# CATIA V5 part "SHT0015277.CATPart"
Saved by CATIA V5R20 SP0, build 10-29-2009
Part number: SHT00105277
Source: Unknown
Bounding box of the stored display mesh (mm): x 989.999 to 1508.999, y -744.979 to -424.979, z 20 to 152.7
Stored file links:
  E:\李燕龙\吉利商用车G3\07 设计变更\ECR0009849--标配底支架后移50mm设计变更\数据图纸\SHT0015277.CATPart
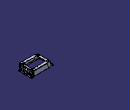
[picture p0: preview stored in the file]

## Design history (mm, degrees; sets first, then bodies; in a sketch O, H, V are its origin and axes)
Set1
  Plane1 to Plane3: stored without definition
  Sketch1 on Plane3, origin (0, -584.9794, 0), H (-1, 0, 0), V (0, 0, 1)
    point P1 (-1154.999, 150.4998)
    line L1 (-1154.999, 150.4998) -> (-1094.999, 150.4998)
    point P2 (-1094.999, 150.4998)
    line L2 (-1094.999, 150.4998) -> (-1034.999, 21.9998)
    point P3 (-1034.999, 21.9998)
    line L3 (-1034.999, 21.9998) -> (-989.999, 21.9998)
    point P4 (-989.999, 21.9998)
    reference projected line E1 (-999.999, 19.9998) -> (-1029.999, 19.9998) from edge [face of Solid11 | face of Solid11]
    reference intersected line E2 through (-1094.999, 0) direction (0, -1) from Plane1
    reference intersected line E3 through (-1034.999, 0) direction (0, -1) from Plane2
    distance L3 E1 = 2
    distance P3 E2 = 60
    distance L1 L3 = 128.5
    distance P2 E3 = 60
    distance P1 P2 = 60
    distance P3 P4 = 45
    horizontal: L1 H, L3 H
    coincidence: L1 P2, L2 P2, L2 P3, L3 P3
  Plane4: stored without definition
  Line1: stored without definition
  DatumSurface1
  DatumCurve1
  DatumSurface2
  DatumSurface3
  Plane5: stored without definition
  Plane6: stored without definition
  DatumCurve2 to DatumCurve5
  Plane7: stored without definition
  DatumPoint1
  DatumPoint2
  DatumCurve6
  DatumCurve7
  Plane8: stored without definition
  Sketch2 on Plane8, origin (225.7297, 0, 484.3783), H (0, 1, 0), V (-0.9064, 0, 0.4224)
    circle A1 centre (-484.2109, -918.6821) radius 1.5
    radius A1 = 1.5
  Plane9: stored without definition
  Sketch3 on Plane9, origin (1057.8408, -768.5663, 0), H (0.5878, 0.809, 0), V (0, 0, 1)
    circle A1 centre (77.1406, 149.6484) radius 1.5
    radius A1 = 1.5
Body1 "SHT0015277.1\\lianjei_AllCATPart.1\\四方焊接螺母.1\\几何体.3" (main body)
  Solid1: solid without history
  Translate1: ToTransfor Solid1, Direction (1, 0, 0), Length 45
  Sketch4 on Plane3, origin (0, -584.9794, 0), H (-1, 0, 0), V (0, 0, 1)
    point P1 (-1143.999, 149.9998)
    line L1 (-1143.999, 149.9998) -> (-1079.999, 149.9998)
    point P2 (-1079.999, 149.9998)
    construction line L2 (-1079.999, 149.9998) -> (-1031.999, 21.9998)
    point P3 (-1031.999, 21.9998)
    line L3 (-1031.999, 21.9998) -> (-989.999, 21.9998)
    point P4 (-989.999, 21.9998)
    reference projected line E1 (-999.999, 19.9998) -> (-1029.999, 19.9998) from edge [face of Solid11 | face of Solid11]
    reference intersected line E2 through (-1094.999, 0) direction (0, -1) from Plane1
    reference intersected line E3 through (-1034.999, 0) direction (0, -1) from Plane2
    line L4 (-1031.999, 21.9998) -> (-1031.999, 46.9998)
    line L5 (-1031.999, 46.9998) -> (-1079.999, 149.9998)
    distance L3 E1 = 2
    distance P3 E2 = 63
    distance L1 L3 = 128
    distance P2 E3 = 45
    distance P1 P2 = 64
    length L4 = 25
    distance P4 P2 H = 90
    horizontal: L1 H, L3 H
    coincidence: L1 P2, L2 P2, L2 P3, L3 P3
    vertical: L4 V
  Sketch5 on Plane2, origin (1034.999, 0, 0), H (0, 1, 0), V (0, 0, 1)
    line L1 (-687.3238, 162.0698) -> (-674.986, 140.7001)
    line L2 (-674.986, 140.7001) -> (-494.986, 140.7001)
    line L3 (-494.986, 140.7001) -> (-481.1375, 164.6862)
    line L4 (-481.1375, 164.6862) -> (-687.3238, 162.0698)
    reference projected line E1 (-670.3672, 140.7001) -> (-499.6048, 140.7001) from edge [face of Solid7 | face of Solid7]
    reference projected line E2 (-677.2954, 144.7001) -> (-678.4501, 146.7001) from edge [face of Solid7 | face of Solid7]
    reference projected line E3 (-492.6766, 144.7001) -> (-491.5219, 146.7001) from edge [face of Solid7 | face of Solid7]
    coincidence: L2 E1, L1 E2, L3 E3
  Sketch6 on face of Pad6, origin (0, 0, 147.9998), H (1, 0, 0), V (0, -1, 0)
    circle A1 centre (1128.999, 469.9941) radius 4.5
    point P2 (1449.999, 469.9941)
    reference projected arc E1 centre (1449.999, 469.9941) radius 4.105 from (1445.9992, 470.9175) to (1453.9988, 469.0707) ccw from edge [face of Solid2 | face of Solid2]
    construction line L1 (1449.999, 469.9941) -> (1128.999, 469.9941)
    circle A2 centre (1007.999, 469.9794) radius 5
    point P3 (1007.999, 469.9794)
    reference projected arc E2 centre (1007.999, 469.9794) radius 5 from (1012.999, 469.9794) to (1007.999, 474.9794) ccw from edge [face of Solid11 | face of Solid11]
    radius A1 = 4.5
    length L1 = 321
    radius A2 = 5
    concentricity: P2 E1, P3 E2
    horizontal: L1 H
Body2
  ThickSurface1: Surface DatumSurface2, TopOffset 2, BotOffset 0
Body3
  Pad1: profile Sketch1, direction (0, 1, 0), length 154, mirrored extent, thin wall 2
  Body4
    Pad2: profile Sketch11, direction (1, 0, 0), up to face of Pad1, thin wall 0, second thickness 2
  Trim1: tool Body4, faces to remove face of Pad2
  Body5
    Pad3: profile Sketch7, direction (-1, 0, 0), up to face of Pad1, opposite side length 154, thin wall 2
    Mirror1: of Pad3, Sketch7, about Plane3
  Trim2: tool Body5
  Sketch7 on Plane2, origin (1034.999, 0, 0), H (0, 1, 0), V (0, 0, 1)
    line L1 (-698.0895, 9.5681) -> (-681.6575, 26.0001)
    line L2 (-681.6575, 26.0001) -> (-621.6575, 26.0001)
    line L3 (-621.6575, 26.0001) -> (-612.1002, 16.4427)
    reference projected line E1 (-624.557, 26.0001) -> (-700.4149, 26.0001) from edge [face of Solid10 | face of Solid10]
    reference projected line E2 (-618.5362, 22.8787) -> (-619.6073, 23.9498) from edge [face of Solid10 | face of Solid10]
    angle L1 L2 = 135
    length L2 = 60
    horizontal: L2 H
    coincidence: L2 E1, L3 E2
  Fillet1: radius 8, on edge [face of Pad2 | face of Pad2] (x2)
  Fillet2: radius 5, on edge [face of Pad2 | face of Pad1]; edge [face of Pad1 | face of Pad2]
  Fillet3: radius 5, on edge [face of Pad2 | face of Pad1]
  Fillet4: radius 7, on edge [face of Mirror1 | face of Mirror1] (x2); edge [face of Pad3 | face of Pad3] (x2)
  Fillet5: radius 3, on edge [face of Pad3 | face of Pad1]; edge [face of Mirror1 | face of Pad1]; edge [face of Pad1 | face of Mirror1]; edge [face of Pad1 | face of Pad3]
  Fillet6: radius 3, on edge [face of Pad1 | face of Pad1]
  Fillet7: radius 10, on edge [face of Pad2 | face of Pad2] (x2)
  Fillet8: radius 3, on edge [face of Pad2 | face of Pad1]; edge [face of Pad1 | face of Pad2]
  Fillet9: radius 3, on edge [face of Pad1 | face of Pad2]
  Fillet10: radius 5, on edge [face of Pad1 | face of Pad3]; edge [face of Mirror1 | face of Pad1]; edge [face of Pad3 | face of Pad1]; edge [face of Pad1 | face of Mirror1]
  Fillet11: radius 5, on edge [face of Mirror1 | face of Mirror1] (x2); edge [face of Pad3 | face of Pad3] (x2)
  Fillet12: radius 5, on edge [face of Pad1 | face of Pad1]
  Fillet13: radius 10, on edge [start face of Pad1 | face of Mirror1]; edge [face of Mirror1 | end face of Pad1]; edge [start face of Pad1 | face of Pad2]; edge [face of Pad2 | end face of Pad1]
  Body6
    Pad4: profile Sketch12, direction (0, 0, -1), length 154, mirrored extent
    Mirror2: of the body so far, about Plane3
  Remove1: tool Body6
  Body7
    Sketch8 on Plane3, origin (0, -584.9794, 0), H (-1, 0, 0), V (0, 0, 1)
      line L1 (-1049.8641, 42.7678) -> (-998.7712, 13.2694)
      reference projected arc E1 centre (-1033.0889, 24.9998) radius 5 from (-1037.6193, 22.8844) to (-1033.0889, 19.9998) ccw from edge [end face of Pad1 | face of Fillet12]
      reference projected line E2 (-1034.999, 21.9998) -> (-989.999, 21.9998) from edge [end face of Pad1 | face of Pad1]
      distance L1 E1 = 12
      angle L1 E2 = 30
    Pad5: profile Sketch8, direction (0, 1, 0), length 140, opposite side length -130, thin wall 0, second thickness 15
    Draft1: PullDir face of Pad5, Angle 40, SupportToDraft (end face of Pad5; start face of Pad5), Neutral face of Pad5
    Fillet14: radius 12, on edge [start face of Pad5 | face of Pad5]; edge [end face of Pad5 | face of Pad5]
    Shell1: IntOffset 2, Face (face of Pad5; face of Pad5; face of Pad5), ExtOffset 0
    Mirror3: of the body so far, about Plane3
  Trim3: tool Body7
  Fillet15: radius 5, on edge [face of Pad1 | face of Mirror3]; edge [face of Pad1 | face of Shell1]
  Fillet16: radius 3, on edge [face of Pad1 | start face of Pad5]; edge [face of Pad1 | face of Mirror3]
Body8 "SHT0015277.1\\lianjei_AllCATPart.1\\四方焊接螺母.3\\几何体.3"
  Solid2: solid without history
Body9 "SHT0015277.1\\lianjei_AllCATPart.1\\四方焊接螺母.4\\几何体.3"
  Solid3: solid without history
  Translate2: ToTransfor Solid3, Direction (1, 0, 0), Length 45
Body10 "SHT0015277.1\\lianjei_AllCATPart.1\\四方焊接螺母.6\\几何体.3"
  Solid4: solid without history
Body11 "SHT0015277.1\\lianjei_AllCATPart.1\\01"
  Solid5: solid without history
  Translate3: ToTransfor Solid5, Direction (0, 1, 0), Length -14
Body12 "55mm--主驾手动标配"
  Solid6: solid without history
Body13 "几何体.9"
  Solid7: solid without history
Body14 "几何体.76"
  Solid8: solid without history
Body15 "几何体.76"
  Solid9: solid without history
  RemoveFace1: RemoveFaces (face of Solid9; face of Solid9; face of Solid9; face of Solid9; face of Solid9; face of Solid9; face of Solid9; face of Solid9; face of Solid9; face of Solid9; face of Solid9; face of Solid9; face of Solid9; face of Solid9; face of Solid9; face of Solid9; face of Solid9; face of Solid9; face of Solid9)
  RemoveFace2: RemoveFaces (face of Solid9; face of Solid9; face of Solid9)
  Thickness1: Thickness 30, Face face of Solid9
  Thickness2: Thickness -60, Face face of Solid9
  Thickness3: Thickness -15, Face face of Solid9
  Thickness4: Thickness 60, Face face of Solid9
  Thickness5: Thickness 25, Face face of Solid9
  Thickness6: Thickness -3, Face face of Solid9
  Sketch9 on face of Solid9, origin (0, -424.9794, 0), H (-1, 0, 0), V (0, 0, 1)
    line L1 (-1095.1537, 166.2166) -> (-1095.1537, 144.922)
    line L2 (-1095.1537, 144.922) -> (-1047.499, 42.8616)
    line L3 (-1047.499, 42.8616) -> (-1047.499, 31.6863)
    line L4 (-1047.499, 31.6863) -> (-1007.8927, 30.5254)
    line L5 (-1007.8927, 30.5254) -> (-969.2202, 170.6736)
    line L6 (-969.2202, 170.6736) -> (-1095.1537, 166.2166)
    reference projected line E1 (-1094.1174, 143.8844) -> (-1038.1581, 24.0382) from edge [face of Pad1 | end face of Pad1]
    reference projected line E2 (-1059.499, 44.9998) -> (-1059.499, 77.9998) from edge [face of Solid9 | face of Solid9]
    distance L2 E1 = 0.5
    distance L3 E2 = 12
    vertical: L1 V, L3 V
  Pocket1: profile Sketch9, direction (0, -1, 0), length 154
  Thickness7: Thickness 0.5, Face face of Pocket1 from Sketch9.L3
  Sketch10 on face of Solid9, origin (0, -445.9794, 0), H (1, 0, 0), V (0, 0, 1)
    line L1 (1098.3551, 147.051) -> (1052.2748, 48.3624)
    line L2 (1052.2748, 48.3624) -> (1131.4653, 48.3624)
    line L3 (1131.4653, 48.3624) -> (1144.1807, 139.054)
    line L4 (1144.1807, 139.054) -> (1098.3551, 147.051)
    reference projected line E1 (1093.6492, 141.6998) -> (1052.2328, 52.9998) from edge [face of Pocket1 from Sketch9.L2 | face of Solid9]
    distance L1 E1 = 2
    horizontal: L2 H
  Pocket2: profile Sketch10, direction (0, 1, 0), up to face of Solid9
  Draft2: PullDir face of Pocket1 from Sketch9.L2, Angle 0, SupportToDraft (face of Solid9; face of Solid9), Neutral face of Pocket1 from Sketch9.L2
  Thickness8: Thickness 2, Face face of Solid9
  Fillet17: radius 3, on edge [face of Pocket2 from Sketch10.L1 | face of Solid9]
  Fillet18: radius 5, on edge [face of Solid9 | face of Pocket1 from Sketch9.L2]
  Fillet19: radius 5, on edge [face of Solid9 | face of Solid9] (x3); edge [face of Solid9 | face of Pocket1 from Sketch9.L3]
  Fillet20: radius 3, on edge [face of Solid9 | face of Solid9]
  Fillet21: radius 15, on edge [face of Solid9 | face of Solid9]
  Fillet22: radius 10, on edge [face of Solid9 | face of Solid9]
  Fillet23: radius 10, on edge [face of Solid9 | face of Pocket1 from Sketch9.L3]
  Sketch11 on Plane2, origin (1034.999, 0, 0), H (0, 1, 0), V (0, 0, 1)
    line L1 (-687.3238, 162.0698) -> (-674.986, 140.7001)
    line L2 (-674.986, 140.7001) -> (-494.986, 140.7001)
    line L3 (-494.986, 140.7001) -> (-481.1375, 164.6862)
    line L4 (-481.1375, 164.6862) -> (-687.3238, 162.0698)
    reference projected line E1 (-670.3672, 140.7001) -> (-499.6048, 140.7001) from edge [face of Solid7 | face of Solid7]
    reference projected line E2 (-677.2954, 144.7001) -> (-678.4501, 146.7001) from edge [face of Solid7 | face of Solid7]
    reference projected line E3 (-492.6766, 144.7001) -> (-491.5219, 146.7001) from edge [face of Solid7 | face of Solid7]
    coincidence: L2 E1, L1 E2, L3 E3
  Fillet24: radius 5, on edge [face of Solid9 | face of Solid9] (x2)
  Sketch12 on face of Pad1, origin (0, 0, 148.4998), H (1, 0, 0), V (0, -1, 0)
    circle A1 centre (1119.999, 469.9941) radius 4.5
    point P2 (1449.999, 469.9941)
    reference projected arc E1 centre (1449.999, 469.9941) radius 4.105 from (1445.9992, 470.9175) to (1453.9988, 469.0707) ccw from edge [face of Solid2 | face of Solid2]
    construction line L1 (1449.999, 469.9941) -> (1119.999, 469.9941)
    circle A2 centre (1007.999, 469.9794) radius 5
    point P3 (1007.999, 469.9794)
    reference projected arc E2 centre (1007.999, 469.9794) radius 5 from (1012.999, 469.9794) to (1007.999, 474.9794) ccw from edge [face of Solid11 | face of Solid11]
    radius A1 = 4.5
    length L1 = 330
    radius A2 = 5
    concentricity: P2 E1, P3 E2
    horizontal: L1 H
  Sketch13 on face of Solid9, origin (0, 0, 152.6998), H (1, 0, 0), V (0, 1, 0)
    circle A1 centre (1119.999, -469.9941) radius 6
    point P1 (1119.999, -469.9941)
    reference projected circle E1 centre (1119.999, -469.9941) radius 4.5 from edge [face of Pad1 | face of Pad4 from Sketch12.A1]
    radius A1 = 6
    concentricity: P1 E1
  Pocket3: profile Sketch13, direction (0, 0, -1), length 5, mirrored extent
Body16 "几何体.31"
  Solid10: solid without history
Body17 "interfacebiao1.2\\几何体.79.2"
  Solid11: solid without history
Body18 "interfacebiao1.2\\几何体.79.1"
  Solid12: solid without history
Body19 "几何体.76"
  Solid13: linked copy from another document
  Symmetry1: Reference Plane3, ToTransfor Solid13
Body20
  Pad6: profile Sketch4, direction (0, 1, 0), length 113, mirrored extent, thin wall 2
  Body21
    Pad7: profile Sketch5, direction (1, 0, 0), up to face of Pad6, thin wall 0, second thickness 2
  Trim4: tool Body21, faces to remove face of Pad7
  Body22
    Pad8: profile Sketch17, direction (-1, 0, 0), up to face of Pad6, opposite side length 154, thin wall 2
    Mirror4: of Pad8, Sketch17, about Plane3
  Trim5: tool Body22
  Sketch14 on face of Pad6, origin (0, 0, 149.9998), H (1, 0, 0), V (0, 1, 0)
    line L1 (1090.999, -481.9794) -> (1143.999, -481.9794)
    point P1 (1143.999, -481.9794)
    line L2 (1143.999, -481.9794) -> (1143.999, -456.9794)
    point P2 (1143.999, -456.9794)
    line L3 (1143.999, -456.9794) -> (1113.999, -456.9794)
    reference projected line E1 (1143.999, -699.9794) -> (1143.999, -469.9794) from edge [face of Pad7 | face of Pad6]
    reference projected line E2 (1149.999, -471.9794) -> (1094.999, -471.9794) from edge [end face of Pad6 | face of Pad6]
    reference projected line E3 (1149.999, -471.9794) -> (1094.999, -471.9794) from edge [end face of Pad6 | face of Pad6]
    point P3 (1090.999, -473.6899)
    line L4 (1090.999, -473.6899) -> (1113.999, -456.9794)
    point P4 (1113.999, -456.9794)
    line L5 (1090.999, -473.6899) -> (1090.999, -481.9794)
    point P5 (1090.999, -481.9794)
    point P6 (1113.999, -456.9794)
    reference intersected line E4 through (0, -584.9794) direction (-1, 0) from Plane3
    point P9 (1143.999, -687.9794)
    point P10 (1143.999, -712.9794)
    point P11 (1090.999, -696.2689)
    point P12 (1113.999, -712.9794)
    point P13 (1090.999, -687.9794)
    point P14 (1113.999, -712.9794)
    line L6 (1090.999, -687.9794) -> (1143.999, -687.9794)
    line L7 (1143.999, -687.9794) -> (1143.999, -712.9794)
    line L8 (1143.999, -712.9794) -> (1113.999, -712.9794)
    line L9 (1090.999, -696.2689) -> (1113.999, -712.9794)
    line L10 (1090.999, -696.2689) -> (1090.999, -687.9794)
    distance L1 E2 = 10
    distance L3 E3 = 15
    angle L4 L2 = 54
    distance P4 L2 = 30
    distance L5 L2 = 53
    horizontal: L1 H
    vertical: L2 V, L5 V
    coincidence: L2 E1, P4 L3, P4 L4
    symmetry: P1 P9 E4, P2 P10 E4, P3 P11 E4, P4 P12 E4, P5 P13 E4, P6 P14 E4, L1 L6 E4, L2 L7 E4, L3 L8 E4, L4 L9 E4, L5 L10 E4
  Pad9: profile Sketch14, direction (0, 0, -1), length 2
  Sketch15 on face of Pad6, origin (0, 0, 21.9998), H (1, 0, 0), V (0, 1, 0)
    point P1 (989.999, -457.9794)
    line L1 (989.999, -457.9794) -> (989.999, -484.5112)
    point P2 (989.999, -484.5112)
    line L2 (989.999, -484.5112) -> (1033.999, -484.5112)
    point P3 (1033.999, -484.5112)
    line L3 (1033.999, -484.5112) -> (1033.999, -457.9794)
    point P4 (1009.999, -457.9794)
    line L4 (1033.999, -457.9794) -> (989.999, -457.9794)
    reference projected line E1 (989.999, -699.9794) -> (989.999, -469.9794) from edge [face of Pad6 | face of Mirror4]
    reference projected line E2 (1034.999, -471.9794) -> (989.999, -471.9794) from edge [end face of Pad6 | face of Pad6]
    reference intersected line E3 through (0, -584.9794) direction (-1, 0) from Plane3
    reference projected line E4 (1031.999, -699.9794) -> (1031.999, -469.9794) from edge [face of Pad6 | face of Pad6]
    point P7 (1033.999, -457.9794)
    point P8 (989.999, -711.9794)
    point P9 (989.999, -685.4477)
    point P10 (1033.999, -685.4477)
    point P11 (1009.999, -711.9794)
    point P12 (1033.999, -711.9794)
    line L5 (989.999, -711.9794) -> (989.999, -685.4477)
    line L6 (989.999, -685.4477) -> (1033.999, -685.4477)
    line L7 (1033.999, -685.4477) -> (1033.999, -711.9794)
    line L8 (1033.999, -711.9794) -> (989.999, -711.9794)
    distance L4 E2 = 14
    distance L3 E4 = 2
    distance P4 P1 = 20
    vertical: L1 V
    perpendicularity: L3 L2
    coincidence: L1 E1, P4 L4
    symmetry: P1 P8 E3, P2 P9 E3, P3 P10 E3, P4 P11 E3, P7 P12 E3, L1 L5 E3, L2 L6 E3, L3 L7 E3, L4 L8 E3
  Pad10: profile Sketch15, direction (0, 0, -1), length 2, opposite side length 12
  Sketch16 on start face of Pad10, origin (0, 0, 33.9998), H (1, 0, 0), V (0, 1, 0)
    point P1 (969.3041, -443.1471)
    line L1 (969.3041, -443.1471) -> (1031.999, -443.1471)
    line L2 (1031.999, -443.1471) -> (1031.999, -486.4848)
    line L3 (1031.999, -486.4848) -> (969.3041, -486.4848)
    line L4 (969.3041, -486.4848) -> (969.3041, -443.1471)
    point P2 (1031.999, -443.1471)
    point P3 (1031.999, -486.4848)
    point P4 (969.3041, -486.4848)
    reference projected line E1 (1031.999, -699.9794) -> (1031.999, -469.9794) from edge [face of Pad6 | face of Pad6]
    reference intersected line E2 through (0, -584.9794) direction (-1, 0) from Plane3
    point P7 (969.3041, -726.8118)
    point P8 (1031.999, -726.8118)
    point P9 (1031.999, -683.474)
    point P10 (969.3041, -683.474)
    line L5 (969.3041, -726.8118) -> (1031.999, -726.8118)
    line L6 (1031.999, -726.8118) -> (1031.999, -683.474)
    line L7 (1031.999, -683.474) -> (969.3041, -683.474)
    line L8 (969.3041, -683.474) -> (969.3041, -726.8118)
    horizontal: L1 H, L3 H
    vertical: L2 V, L4 V
    coincidence: L2 E1
    symmetry: P1 P7 E2, P2 P8 E2, P3 P9 E2, P4 P10 E2, L1 L5 E2, L2 L6 E2, L3 L7 E2, L4 L8 E2
  Pocket4: profile Sketch16, direction (0, 0, -1), up to face of Pad6
  Thickness9: Thickness 12, Face (face of Pad10 from Sketch15.L4; face of Pad10 from Sketch15.L8)
  Fillet25: radius 5, on edge [end face of Pad6 | start face of Pad10]; edge [face of Pad10 from Sketch15.L4 | start face of Pad10]; edge [start face of Pad10 | start face of Pad6]; edge [face of Pad10 from Sketch15.L8 | start face of Pad10]
  Fillet26: radius 15, on edge [face of Pad9 from Sketch14.L4 | end face of Pad6]; edge [start face of Pad6 | face of Pad9 from Sketch14.L9]; edge [face of Pad9 from Sketch14.L9 | face of Pad9 from Sketch14.L8]; edge [face of Pad9 from Sketch14.L3 | face of Pad9 from Sketch14.L4]; edge [face of Pad10 | face of Pad10 from Sketch15.L8]; edge [face of Pad10 from Sketch15.L4 | face of Pad10]
  Sketch17 on Plane2, origin (1034.999, 0, 0), H (0, 1, 0), V (0, 0, 1)
    line L1 (-678.0895, 9.5681) -> (-661.6575, 26.0001)
    line L2 (-661.6575, 26.0001) -> (-621.6575, 26.0001)
    line L3 (-621.6575, 26.0001) -> (-612.1002, 16.4427)
    reference projected line E1 (-624.557, 26.0001) -> (-700.4149, 26.0001) from edge [face of Solid10 | face of Solid10]
    reference projected line E2 (-618.5362, 22.8787) -> (-619.6073, 23.9498) from edge [face of Solid10 | face of Solid10]
    angle L1 L2 = 135
    length L2 = 40
    horizontal: L2 H
    coincidence: L2 E1, L3 E2
  Fillet27: radius 8, on edge [face of Pad7 | face of Pad7] (x2)
  Fillet28: radius 5, on edge [face of Pad7 | face of Pad6]; edge [face of Pad6 | face of Pad7]
  Fillet29: radius 5, on edge [face of Pad7 | face of Pad6]
  Fillet30: radius 7, on edge [face of Mirror4 | face of Mirror4] (x2); edge [face of Pad8 | face of Pad8] (x2)
  Fillet31: radius 3, on edge [face of Pad8 | face of Pad6]; edge [face of Mirror4 | face of Pad6]; edge [face of Pad6 | face of Mirror4]; edge [face of Pad6 | face of Pad8]
  Fillet32: radius 3, on edge [face of Pad6 | face of Mirror4]
  Fillet33: radius 10, on edge [face of Pad7 | face of Pad7] (x2)
  Fillet34: radius 3, on edge [face of Pad7 | face of Pad6]; edge [face of Pad6 | face of Pad7]
  Fillet35: radius 3, on edge [face of Pad6 | face of Pad7]
  Fillet36: radius 5, on edge [face of Pad6 | face of Pad8]; edge [face of Mirror4 | face of Pad6]; edge [face of Pad8 | face of Pad6]; edge [face of Pad6 | face of Mirror4]
  Fillet37: radius 5, on edge [face of Mirror4 | face of Mirror4] (x2); edge [face of Pad8 | face of Pad8] (x2)
  Fillet38: radius 5, on edge [face of Mirror4 | face of Pad6]
  Body23
    Pad11: profile Sketch6, direction (0, 0, -1), length 154, mirrored extent
    Mirror5: of the body so far, about Plane3
  Remove2: tool Body23
  Body24
    Sketch18 on Plane3, origin (0, -584.9794, 0), H (-1, 0, 0), V (0, 0, 1)
      line L1 (-1045.8666, 48.7669) -> (-1004.1495, 7.0497)
      construction arc A1 centre (-1031.6583, 29.8659) radius 5 from (-1036.5819, 28.9952) to (-1032.9524, 25.0363) ccw
      reference projected line E1 (-1034.999, 21.9998) -> (-989.999, 21.9998) from edge [end face of Pad6 | face of Pad6]
      construction arc A2 centre (-1031.999, 24.9998) radius 5 from (-1036.999, 24.9998) to (-1031.999, 19.9998) ccw
      angle L1 E1 = 45
      distance L1 A2 = 12
      fix: A2
    Pad12: profile Sketch18, direction (0, 1, 0), length 101, opposite side length -93, thin wall 0, second thickness 15
    Draft3: PullDir face of Pad12, Angle 25, SupportToDraft (end face of Pad12; start face of Pad12), Neutral face of Pad12
    Fillet39: radius 8, on edge [start face of Pad12 | face of Pad12]; edge [end face of Pad12 | face of Pad12]
    Shell2: IntOffset 2, Face (face of Pad12; face of Pad12; face of Pad12), ExtOffset 0
    Mirror6: of the body so far, about Plane3
  Trim6: tool Body24
  Fillet40: radius 5, on edge [face of Pad6 | face of Mirror6]; edge [face of Shell2 | face of Pad6]
  Fillet41: radius 3, on edge [face of Pad6 | face of Mirror6]; edge [face of Pad6 | end face of Pad12]
  Fillet42: radius 10, on edge [face of Pad6 | face of Pad6]
  Fillet43: radius 8, on edge [face of Pad6 | face of Pad6]
  Sketch19 on face of Pad7, origin (0, 0, 140.7001), H (1, 0, 0), V (0, 1, 0)
    line L1 (1187.5226, -498.2263) -> (1132.4108, -512.9934)
    point P2 (1124.999, -514.9794)
    line L2 (1124.999, -522.6527) -> (1124.999, -647.3062)
    point P3 (1124.999, -654.9794)
    line L3 (1132.4108, -656.9654) -> (1201.4524, -675.465)
    line L4 (1201.4524, -675.465) -> (1187.5226, -498.2263)
    reference intersected line E1 through (0, -584.9794) direction (-1, 0) from Plane3
    reference intersected line E2 through (0, -584.9794) direction (-1, 0) from Plane3
    reference intersected line E3 through (1034.999, 0) direction (0, 1) from Plane2
    reference intersected line E4 through (0, -584.9794) direction (-1, 0) from Plane3
    reference intersected line E5 through (0, -584.9794) direction (-1, 0) from Plane3
    arc A1 centre (1134.999, -522.6527) radius 10 from (1132.4108, -512.9934) to (1124.999, -522.6527) ccw
    arc A2 centre (1134.999, -647.3062) radius 10 from (1124.999, -647.3062) to (1132.4108, -656.9654) ccw
    distance P2 E1 = 70
    distance P3 E2 = 70
    distance L2 E3 = 90
    angle L1 E4 = 15
    angle L3 E5 = 15
    radius A1 = 10
    radius A2 = 10 {= Sketch19.radius(A1)}
    vertical: L2 V
    coincidence: L1 P2, L2 P2, L2 P3, L3 P3
    tangency: A1 L1, A1 L2, A2 L2, A2 L3
  Pocket5: profile Sketch19, direction (0, 0, -1), length 154, mirrored extent
  Fillet44: radius 10, on edge [face of Pocket5 from Sketch19.L1 | face of Pad7]; edge [face of Pad7 | face of Pocket5 from Sketch19.L3]; edge [face of Pad9 | face of Pad9 from Sketch14.L3]; edge [face of Pad9 from Sketch14.L8 | face of Pad9]
  Body25
    Pad13: profile Sketch20, direction (0.9064, 0, -0.4224), length 113, mirrored extent, deactivated
    Mirror7: of the body so far, about Plane3, deactivated
  Remove3: tool Body25, deactivated
  Sketch20 on face of Pad6, origin (831.6828, 0, -387.5803), H (0, 1, 0), V (0.4224, 0, 0.9064)
    circle A1 centre (-552.486, 566.0013) radius 2.5
    point P1 (-552.486, 566.0013)
    point P2 (-517.6404, 558.4138)
    point P3 (-552.986, 566.5013)
    point P4 (-551.986, 565.5013)
    construction line L1 (-552.986, 566.5013) -> (-551.986, 565.5013)
    point P5 (-552.486, 566.0013)
    circle A2 centre (-494.486, 571.8877) radius 1.8
    point P6 (-494.486, 571.8877)
    reference projected circle E1 centre (-494.486, 571.8877) radius 2 from edge of DatumCurve6
    circle A3 centre (-494.486, 484.8943) radius 1.8
    point P7 (-494.486, 484.8943)
    reference projected circle E2 centre (-494.486, 484.8943) radius 2 from edge of DatumCurve7
    radius A1 = 2.5
    radius A2 = 1.8
    radius A3 = 1.8
    fix: P3, P4
    midpoint: P5 L1
    coincidence: P1 P5
    concentricity: P6 E1, P7 E2
Body26 "几何体.76"
  Solid14: solid without history
  RemoveFace3: RemoveFaces (face of Solid14; face of Solid14; face of Solid14; face of Solid14; face of Solid14; face of Solid14; face of Solid14; face of Solid14; face of Solid14; face of Solid14; face of Solid14; face of Solid14; face of Solid14; face of Solid14; face of Solid14; face of Solid14; face of Solid14; face of Solid14; face of Solid14)
  RemoveFace4: RemoveFaces (face of Solid14; face of Solid14; face of Solid14)
  Thickness10: Thickness 30, Face face of Solid14
  Thickness11: Thickness -60, Face face of Solid14
  Thickness12: Thickness -5, Face face of Solid14
  Thickness13: Thickness 250, Face face of Solid14
  Thickness14: Thickness 25, Face face of Solid14
  Thickness15: Thickness -3, Face face of Solid14
  Thickness16: Thickness 37, Face face of Solid14
  RemoveFace5: RemoveFaces (face of Solid14; face of Solid14)
  Thickness17: Thickness 11, Face face of Solid14
  Thickness18: Thickness 11, Face face of Solid14
  Thickness19: Thickness 3, Face (face of Solid14; face of Solid14)
  Sketch21 on face of Solid14, origin (0, -424.9794, 0), H (-1, 0, 0), V (0, 0, 1)
    line L1 (-1083.6835, 173.2821) -> (-1083.6835, 151.9875)
    line L2 (-1083.6835, 151.9875) -> (-1034.499, 46.4459)
    line L3 (-1034.499, 46.4459) -> (-1034.499, 31.6863)
    line L4 (-1034.499, 31.6863) -> (-1008.071, 23.263)
    line L5 (-1008.071, 23.263) -> (-969.3985, 163.4112)
    line L6 (-969.3985, 163.4112) -> (-1083.6835, 173.2821)
    reference projected line E1 (-1038.0739, 55.3006) -> (-1084.2917, 154.4763) from edge [end face of Pad6 | face of Pad6]
    reference projected line E2 (-1033.999, 19.9998) -> (-1033.999, 56.4133) from edge [end face of Pad6 | face of Pad6]
    distance L2 E1 = 0.5
    distance L3 E2 = 0.5
    vertical: L1 V, L3 V
  Pocket6: profile Sketch21, direction (0, -1, 0), length 154
  Sketch22 on Plane6, origin (272.733, 0, 462.9816), H (0, 1, 0), V (-0.9064, 0, 0.4224)
    construction line L1 (-467.1178, -868.5925) -> (-425.9794, -916.3376)
    line L2 (-406.2843, -966.1543) -> (-379.1077, -808.5454)
    line L3 (-379.1077, -808.5454) -> (-480.814, -749.711)
    line L4 (-480.814, -749.711) -> (-472.547, -864.3883)
    construction line L5 (-435.775, -1005.688) -> (-333.3782, -1023.8102)
    construction line L6 (-333.3782, -1023.8102) -> (-254.2923, -1158.1424)
    point P5 (-333.3782, -1023.8102)
    construction line L7 (-447.0206, -878.7204) -> (-428.6464, -904.7203)
    point P8 (-467.9794, -867.5925)
    reference projected line E1 (-424.9794, -867.5925) -> (-482.9794, -867.5925) from edge [face of Pocket6 from Sketch21.L1 | face of Solid14]
    reference projected line E2 (-471.9794, -868.2954) -> (-471.9794, -865.2972) from edge [end face of Pad6 | face of Fillet29]
    construction line L8 (-425.9794, -1080.3747) -> (-425.9794, -916.3376)
    construction line L9 (-478.2161, -868.5925) -> (-467.1178, -868.5925)
    reference projected line E3 (-424.9794, -867.5925) -> (-482.9794, -867.5925) from edge [face of Pocket6 from Sketch21.L1 | face of Solid14]
    reference projected line E4 (-424.9794, -886.6671) -> (-424.9794, -1216.5572) from edge [face of Solid14 | face of Solid14]
    point P9 (-425.9794, -916.3376)
    point P11 (-467.1178, -868.5925)
    arc A1 centre (-576.9574, -1004.8286) radius 175 from (-406.2843, -966.1543) to (-472.547, -864.3883) ccw
    point P13 (-425.9794, -916.3376)
    point P15 (-425.9794, -1080.3747)
    point P17 (-446.5486, -892.4651)
    angle L1 L7 = -5.5
    distance P8 E2 = 4
    distance L9 E3 = 1
    distance L8 E4 = 1
    radius A1 = 175
    distance P17 A1 = 2.8605 (reference)
    coincidence: L1 P5, P8 L1, P8 E1, A1 P13, P13 L8, P9 A1, A1 P11, P15 L2
    fix: L7
    midpoint: P17 L1
  Pocket7: profile Sketch22, direction (-0.4224, 0, -0.9064), length 154, mirrored extent
  Sketch23 on face of Solid14, origin (0, 0, 39.9998), H (1, 0, 0), V (0, -1, 0)
    point P1 (1037.499, 464.849)
    line L1 (1037.499, 464.849) -> (1138.7641, 424.9794)
    line L2 (1138.7641, 424.9794) -> (1123.8618, 349.4904)
    line L3 (1123.8618, 349.4904) -> (989.177, 381.3252)
    line L4 (989.177, 381.3252) -> (1037.499, 464.849)
    point P5 (1037.499, 464.849)
    coincidence: P1 P5
  Pocket8: profile Sketch23, direction (0, 0, 1), length 154, deactivated
  Thickness20: Thickness 0, Face face of Pocket6 from Sketch21.L3
  RemoveFace6: RemoveFaces face of Solid14
  RemoveFace7: RemoveFaces (face of Solid14; face of Solid14; face of Solid14; face of Solid14)
  Thickness21: Thickness 2, Face (face of Solid14; face of Solid14; face of Solid14)
  Draft4: PullDir face of Solid14, Angle -15, SupportToDraft face of Pocket7 from Sketch22.L1, Neutral face of Solid14, deactivated
  Fillet45: radius 100, on edge [face of Pocket7 from Sketch22.A1 | face of Solid14]
  Fillet46: on edge [face of Solid14 | face of Fillet45]
  Fillet47: on edge [face of Solid14 | face of Solid14]
  Sketch24 on face of Solid14, origin (0, -482.9794, 0), H (1, 0, 0), V (0, 0, 1)
    line L1 (1085.9748, 158.1879) -> (1085.9748, 142.6998)
    point P2 (1085.9748, 142.6998)
    line L2 (1085.9748, 142.6998) -> (1072.218, 146.3859)
    line L3 (1072.218, 146.3859) -> (1071.7929, 159.5129)
    line L4 (1071.7929, 159.5129) -> (1085.9748, 158.1879)
    reference projected line E1 (1083.6646, 151.947) -> (1034.9761, 47.4695) from edge [face of Pocket6 from Sketch21.L2 | face of Solid14]
    line L5 (1026.0567, 53.1109) -> (1039.1702, 46.9998)
    point P6 (1039.1702, 46.9998)
    line L6 (1039.1702, 46.9998) -> (1039.1702, 26.6162)
    line L7 (1039.1702, 26.6162) -> (999.7926, 31.0661)
    line L8 (999.7926, 31.0661) -> (1026.0567, 53.1109)
    reference projected line E2 (1083.6646, 151.947) -> (1034.9761, 47.4695) from edge [face of Pocket6 from Sketch21.L2 | face of Solid14]
    reference projected line E3 (1083.6646, 151.947) -> (1034.9761, 47.4695) from edge [face of Pocket6 from Sketch21.L2 | face of Solid14]
    construction line L9 (1104.499, 152.6998) -> (1036.499, 152.6998)
    construction line L10 (1075.1495, 39.9998) -> (1085.5597, 39.9998)
    distance P2 E1 = 6
    distance P2 L9 = 10
    distance P6 E2 = 4
    distance P6 L10 = 7
    angle L2 L1 = 75
    vertical: L1 V, L6 V
    perpendicularity: L5 E3
    fix: L9, L10
  Pocket9: profile Sketch24, direction (0, 1, 0), length 154, opposite side length 5
  Fillet48: radius 3, on edge [face of Pocket9 from Sketch24.L1 | face of Pocket9 from Sketch24.L2]
  Fillet49: radius 4, on edge [face of Pocket6 from Sketch21.L2 | face of Pocket7 from Sketch22.A1]
  Fillet50: radius 2, on edge [face of Pocket9 from Sketch24.L5 | face of Pocket9 from Sketch24.L6]
  Shell3: IntOffset 2, Face (face of Solid14; face of Solid14; face of Solid14; face of Pocket9 from Sketch24.L6; face of Fillet48; face of Solid14; face of Solid14; face of Solid14; face of Solid14; face of Solid14; face of Solid14; face of Solid14; face of Solid14; face of Solid14; face of Solid14; face of Solid14), ExtOffset 0
  Sketch25 on face of Solid14, origin (0, -445.9794, 0), H (1, 0, 0), V (0, 0, 1)
    line L1 (1098.1482, 146.9597) -> (1043.5233, 52.7315)
    line L2 (1043.5233, 52.7315) -> (1122.7138, 52.7315)
    line L3 (1122.7138, 52.7315) -> (1143.0874, 134.9425)
    line L4 (1143.0874, 134.9425) -> (1098.1482, 146.9597)
    reference projected line E1 (1092.9877, 142.0455) -> (1043.8915, 57.3545) from edge [face of Pocket6 from Sketch21.L2 | face of Solid14]
    distance L1 E1 = 2
    horizontal: L2 H
  Pocket10: profile Sketch25, direction (0, 1, 0), up to face of Solid14, opposite side length 24, deactivated
  Draft5: PullDir face of Pocket6 from Sketch21.L2, Angle 0, SupportToDraft (face of Solid14; face of Solid14), Neutral face of Pocket6 from Sketch21.L2, deactivated
  RemoveFace8: RemoveFaces (face of Solid14; face of Solid14)
  Fillet51: radius 3, on edge [face of Solid14 | face of Pocket9 from Sketch24.L1]
  Sketch26 on Plane2, origin (1034.999, 0, 0), H (0, 1, 0), V (0, 0, 1)
    line L1 (-687.3238, 162.0698) -> (-674.986, 140.7001)
    line L2 (-674.986, 140.7001) -> (-494.986, 140.7001)
    line L3 (-494.986, 140.7001) -> (-481.1375, 164.6862)
    line L4 (-481.1375, 164.6862) -> (-687.3238, 162.0698)
    reference projected line E1 (-670.3672, 140.7001) -> (-499.6048, 140.7001) from edge [face of Solid7 | face of Solid7]
    reference projected line E2 (-677.2954, 144.7001) -> (-678.4501, 146.7001) from edge [face of Solid7 | face of Solid7]
    reference projected line E3 (-492.6766, 144.7001) -> (-491.5219, 146.7001) from edge [face of Solid7 | face of Solid7]
    coincidence: L2 E1, L1 E2, L3 E3
  Sketch27 on face of Pad1, origin (0, 0, 148.4998), H (1, 0, 0), V (0, -1, 0)
    circle A1 centre (1119.999, 469.9941) radius 4.5
    point P2 (1449.999, 469.9941)
    reference projected arc E1 centre (1449.999, 469.9941) radius 4.105 from (1445.9992, 470.9175) to (1453.9988, 469.0707) ccw from edge [face of Solid2 | face of Solid2]
    construction line L1 (1449.999, 469.9941) -> (1119.999, 469.9941)
    circle A2 centre (1007.999, 469.9794) radius 5
    point P3 (1007.999, 469.9794)
    reference projected arc E2 centre (1007.999, 469.9794) radius 5 from (1012.999, 469.9794) to (1007.999, 474.9794) ccw from edge [face of Solid11 | face of Solid11]
    radius A1 = 4.5
    length L1 = 330
    radius A2 = 5
    concentricity: P2 E1, P3 E2
    horizontal: L1 H
  Sketch28 on face of Solid14, origin (0, 0, 152.6998), H (1, 0, 0), V (0, 1, 0)
    circle A1 centre (1128.999, -469.9794) radius 6
    point P1 (1128.999, -469.9794)
    construction circle A2 centre (1128.999, -469.9794) radius 4.5
    reference projected line E1 (1464.499, -429.9794) -> (1464.499, -480.9794) from edge [face of Solid14 | face of Solid14]
    reference projected line E2 (1464.5718, -424.9794) -> (1166.946, -424.9794) from edge [face of Solid14 | face of Fillet46]
    radius A1 = 6
    distance P1 E1 = 335.5
    distance E2 P1 = 45
    concentricity: P1 A2
  Pocket11: profile Sketch28, direction (0, 0, -1), length 5, mirrored extent
  Thickness22: Thickness 25, Face face of Solid14
  Sketch29 on face of Solid14, origin (0, 0, 39.9998), H (1, 0, 0), V (0, -1, 0)
    line L1 (1051.104, 491.2514) -> (1051.104, 474.2599)
    line L2 (1051.104, 474.2599) -> (1090.817, 449.9794)
    line L3 (1090.817, 449.9794) -> (1165.6669, 449.9794)
    line L4 (1165.6669, 449.9794) -> (1140.1691, 486.8676)
    line L5 (1140.1691, 486.8676) -> (932.6621, 567.3429)
    line L6 (932.6621, 567.3429) -> (1051.104, 491.2514)
    reference projected line E1 (1071.2013, 449.9794) -> (1437.7968, 449.9794) from edge [face of Solid14 | face of Solid14]
    construction line L7 (1042.8785, 465.2238) -> (1133.7096, 409.6898)
    construction line L8 (1043.104, 450.0187) -> (1043.104, 455.4817)
    distance L2 L7 = 12
    distance L1 L8 = 8
    coincidence: L3 E1
    fix: L7, L8
  Pocket12: profile Sketch29, direction (0, 0, 1), length 15
  Sketch30 on face of Solid14, origin (0, 0, 39.9998), H (1, 0, 0), V (0, -1, 0)
    line L1 (1034.6702, 483.9794) -> (1048.635, 483.9794)
    line L2 (1048.635, 483.9794) -> (1048.635, 473.9794)
    line L3 (1048.635, 473.9794) -> (1034.6702, 473.9794)
    line L4 (1034.6702, 473.9794) -> (1034.6702, 483.9794)
    reference projected line E1 (1042.6054, 483.9794) -> (1038.999, 483.9794) from edge [face of Solid14 | face of Solid14]
    reference projected line E2 (1039.1702, 483.9794) -> (1039.1702, 470.675) from edge [face of Pocket9 from Sketch24.L6 | face of Solid14]
    distance L4 E2 = 4.5
    distance L3 L1 = 10
    horizontal: L1 H, L3 H
    vertical: L2 V, L4 V
    coincidence: E1 L1
  Pad14: profile Sketch30, direction (0, 0, 1), length 2
  Thickness23: Thickness 5, Face face of Pad14
  Thickness24: Thickness 2, Face face of Pad14 from Sketch30.L3
  Fillet52: radius 3, on edge [face of Pad14 | face of Pad14 from Sketch30.L4]; edge [face of Pad14 from Sketch30.L4 | face of Pad14 from Sketch30.L3]; edge [face of Pocket9 from Sketch24.L6 | face of Pad14 from Sketch30.L3]
  Fillet53: radius 10, on edge [face of Pocket12 from Sketch29.L2 | face of Pocket12 from Sketch29.L1]
  Fillet54: radius 15, on edge [face of Pocket12 | face of Pocket12 from Sketch29.L2]
  Fillet55: radius 3, on edge [face of Pocket12 from Sketch29.L1 | face of Solid14]
  Fillet56: radius 8, on edge [face of Solid14 | face of Pocket9 from Sketch24.L5]; edge [face of Solid14 | face of Pocket9 from Sketch24.L2]
  RemoveFace9: RemoveFaces (face of Solid14; face of Solid14; face of Solid14; face of Solid14; face of Shell3; face of Shell3)
  Thickness25: Thickness -2, Face face of Solid14
  Fillet57: radius 4, on edge [face of Shell3 | face of Solid14] (x2)
  Sketch31 on face of Shell3, origin (0, -426.9794, 0), H (1, 0, 0), V (0, 0, 1)
    circle A1 centre (1173.9992, 125.6998) radius 2.5
    point P1 (1173.9992, 125.6998)
    reference projected circle E1 centre (1173.9992, 125.6998) radius 1.75 from edge of DatumCurve2
    circle A2 centre (1173.9992, 65.6998) radius 2.5
    point P2 (1173.9992, 65.6998)
    reference projected circle E2 centre (1173.9992, 65.6998) radius 2.75 from edge of DatumCurve3
    radius A1 = 2.5
    radius A2 = 2.5
    concentricity: P1 E1, P2 E2
  Pocket13: profile Sketch31, direction (0, 1, 0), length 113, mirrored extent, deactivated
Body27 "几何体.76"
  Solid15: linked copy from another document
  Symmetry2: Reference Plane3, ToTransfor Solid15
Body28
  Sketch32 on face of Pad6, origin (0, 0, 21.9998), H (1, 0, 0), V (0, 1, 0)
    line L1 (1147.5475, -424.8273) -> (1036.3828, -454.5533)
Body29
  ThickSurface2: Surface DatumSurface3, TopOffset 2, BotOffset 0
Body30 "几何体.31"
  Solid16: solid without history
Body31 "几何体.9"
  Solid17: solid without history
  Body32
    Pad15: profile Sketch33, direction (1, 0, 0), length 113, mirrored extent
    Mirror8: of the body so far, about Plane7
  Remove4: tool Body32
  Sketch33 on face of Solid17, origin (1473.9992, 0, 0), H (0, 1, 0), V (0, 0, 1)
    circle A1 centre (-454.9991, 128.0003) radius 1.8
    reference projected circle E1 centre (-454.9991, 128.0003) radius 2.25 from edge of DatumCurve4
    circle A2 centre (-454.9991, 66.0003) radius 1.8
    point P2 (-454.9991, 66.0003)
    reference projected circle E2 centre (-454.9991, 66.0003) radius 2.25 from edge of DatumCurve5
    radius A1 = 1.8
    radius A2 = 1.8
    concentricity: A1 E1, P2 E2
Body33
  Pad16: profile Sketch2, direction (0.4224, 0, 0.9064), length 40, opposite side length -20
  Pad17: profile Sketch2, direction (-0.4224, 0, -0.9064), length 40, opposite side length -20
  Sketch34 on face of Solid15, origin (0, -685.9794, 0), H (-1, 0, 0), V (0, 0, 1)
    circle A1 centre (-1145.5747, 149.0892) radius 1.5
    radius A1 = 1.5
  Pad18: profile Sketch34, direction (0, -1, 0), length 20
  Pad19: profile Sketch3, direction (0.809, -0.5878, 0), length 10, mirrored extent
  Mirror9: of Pad16, Sketch2, Pad17, Sketch2, Pad18, Sketch34, Pad19, Sketch3, about Plane3
Body34 "变更孔位"
  Solid18: solid without history
  Translate4: ToTransfor Solid18, FirstPoint vertex [face of Solid18 | face of Solid18 | face of Solid18], SecondPoint vertex [face of Solid17 | face of Solid17 | face of Solid17]
Body35 "几何体.31B"
  Solid19: solid without history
